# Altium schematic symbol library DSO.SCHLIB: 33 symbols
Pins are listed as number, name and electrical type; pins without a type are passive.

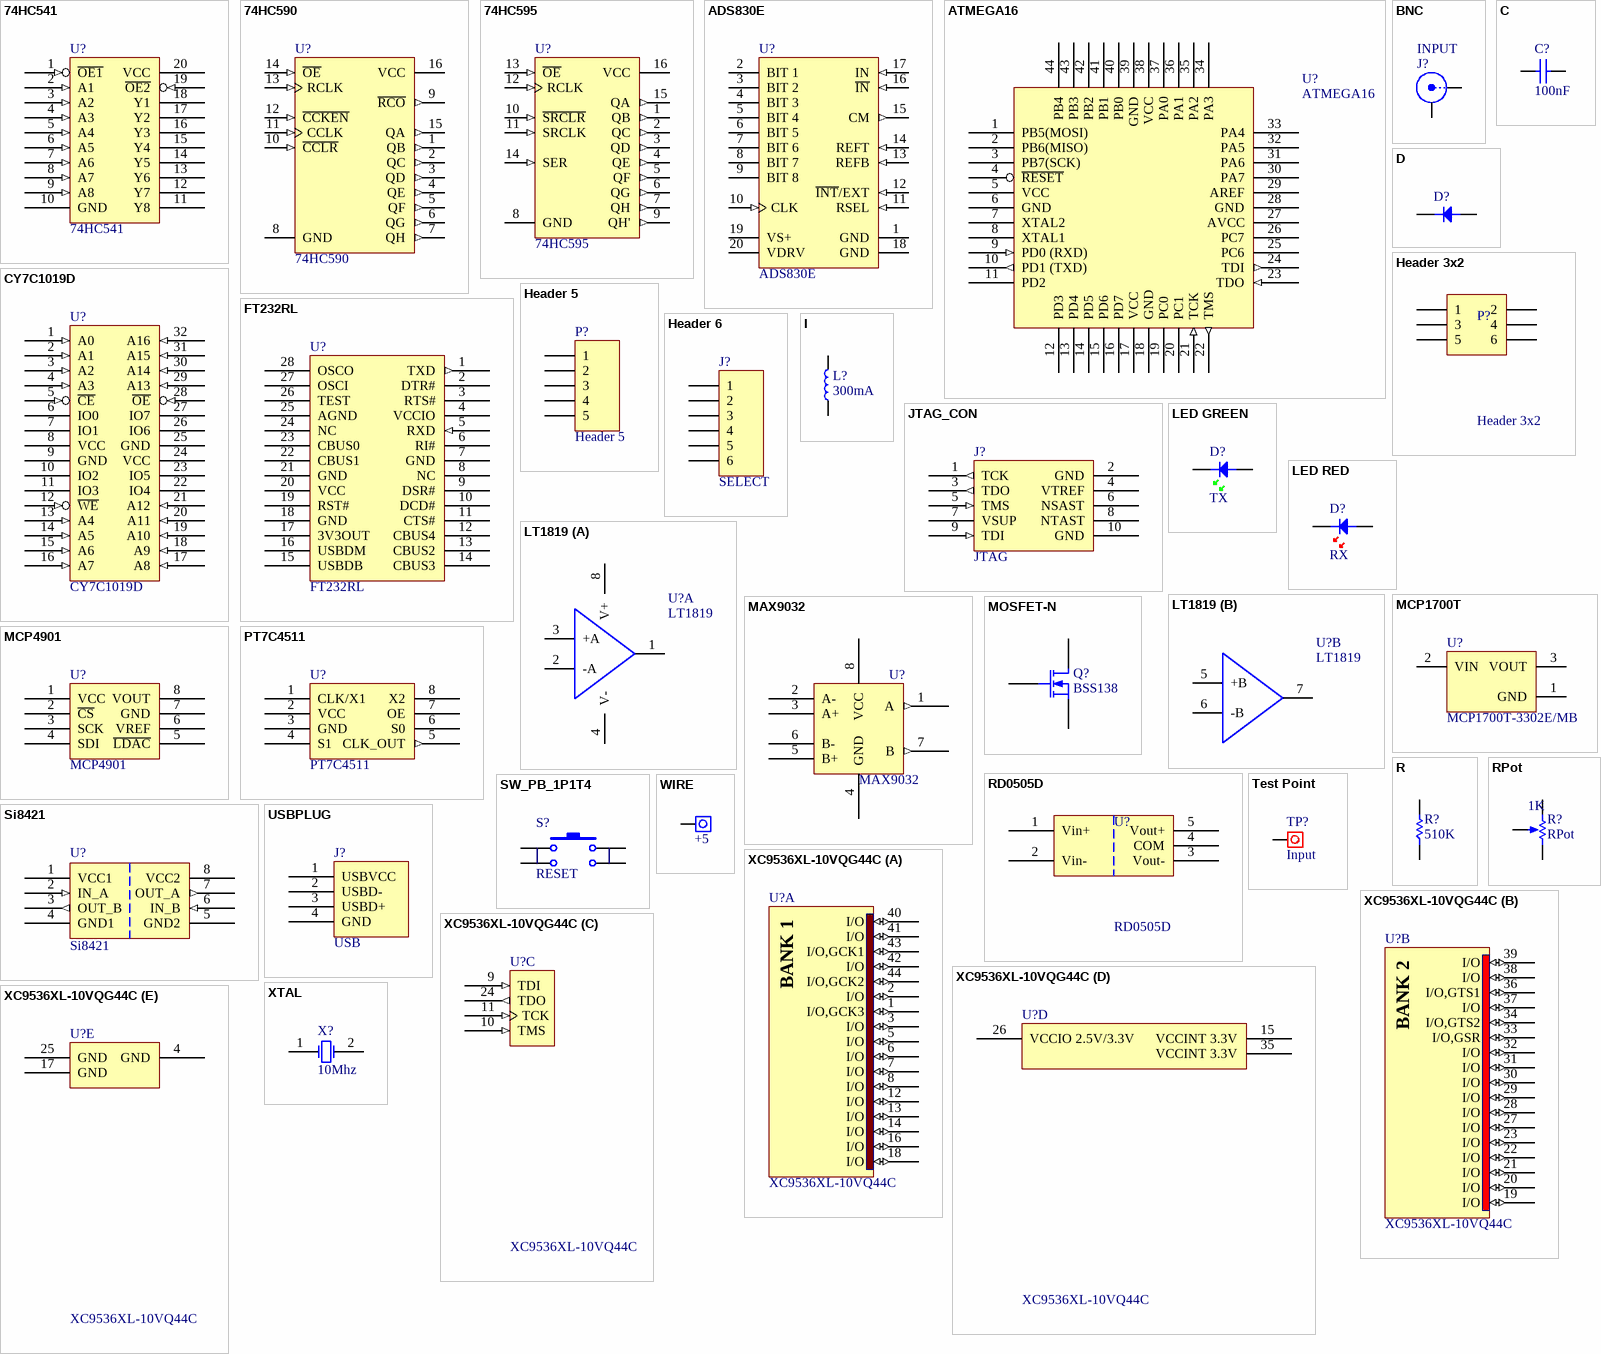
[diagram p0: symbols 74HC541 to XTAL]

## 74HC541
designator U?
(ADV) Octal Buffer, Line Driver; Reviewed by: RM - 2018/08/05
footprint SOT163-1_N (SOIC, 20-Leads, Body 12.7x7.5mm, Pitch 1.27mm, IPC Medium Density)
pins: 1 ~{OE1} (in), 2 A1 (in), 3 A2 (in), 4 A3 (in), 5 A4 (in), 6 A5 (in), 7 A6 (in), 8 A7 (in), 9 A8 (in), 10 GND (power), 11 Y8 (hiz), 12 Y7 (hiz), 13 Y6 (hiz), 14 Y5 (hiz), 15 Y4 (hiz), 16 Y3 (hiz), 17 Y2 (hiz), 18 Y1 (hiz), 19 ~{OE2} (in), 20 VCC (power)

## 74HC590
designator U?
8-Bit Binary Counter Register; Reviewed by: RM - 2018/08/05
footprint SOIC-16 (SOIC-16 Footprint)
pins: 1 QB (out), 2 QC (out), 3 QD (out), 4 QE (out), 5 QF (out), 6 QG (out), 7 QH (out), 8 GND (power), 9 ~{RCO} (out), 10 ~{CCLR} (in), 11 CCLK (in), 12 ~{CCKEN} (in), 13 RCLK (in), 14 ~{OE} (in), 15 QA (out), 16 VCC (power)

## 74HC595
designator U?
(ADV)  8 Bit Shift Register
footprint SOIC-16 (SOIC-16 Footprint)
pins: 1 QB (out), 2 QC (out), 3 QD (out), 4 QE (out), 5 QF (out), 6 QG (out), 7 QH (out), 8 GND (power), 9 QH' (out), 10 ~{SRCLR} (in), 11 SRCLK (in), 12 RCLK (in), 13 ~{OE} (in), 14 SER (in), 15 QA (out), 16 VCC (power)

## ADS830E
designator U?
8-Bit, 60 MSPS ADC Single-Ended / Differential Input, Internal / External Reference and Programmble Input Range, -40 to 85 degC, 20-pin SOP (DBQ20), Green (RoHS & no Sb/Br); Reviewed by: RM - 2018/08/05
footprint TI-DBQ20_L (SOP, 20-Leads, Body 8.65x3.9mm, Pitch 0.635mm, IPC High Density)
pins: 1 GND (power) "Ground", 2 BIT 1 (hiz) "Data Bit 1 (D7) (MSB)", 3 BIT 2 (hiz) "Data Bit 2 (D6)", 4 BIT 3 (hiz) "Data Bit 3 (D5)", 5 BIT 4 (hiz) "Data Bit 4 (D4)", 6 BIT 5 (hiz) "Data Bit 5 (D3)", 7 BIT 6 (hiz) "Data Bit 6 (D2)", 8 BIT 7 (hiz) "Data Bit 7 (D1)", 9 BIT 8 (hiz) "Data Bit 8 (D0) (LSB)", 10 CLK (in) "Convert Clock", 11 RSEL (in) "Input Range Select: HI = 2V; LO = 1V", 12 ~{INT}/EXT (in) "Reference Select: HI = External; LO = Internal", 13 REFB (in) "Bottom Reference", 14 REFT (in) "Top Reference", 15 CM (out) "Common-Mode Voltage Output", 16 ~{IN} (in) "Complementary Input", 17 IN (in) "Analog Input", 18 GND (power) "Ground", 19 VS+ (power) "+5V Supply", 20 VDRV (power) "Output Logic Driver Supply Voltage"

## ATMEGA16
designator U?
ATMEGA16 Microcontroller; Reviewed by: RM - 2018/08/05
footprint QFP-48
pins: 1 PB5(MOSI), 2 PB6(MISO), 3 PB7(SCK), 4 ~{RESET}, 5 VCC, 6 GND, 7 XTAL2, 8 XTAL1, 9 PD0 (RXD) (in), 10 PD1 (TXD) (out), 11 PD2, 12 PD3, 13 PD4, 14 PD5, 15 PD6, 16 PD7, 17 VCC, 18 GND, 19 PC0, 20 PC1, 21 TCK (in), 22 TMS (out), 23 TDO (in), 24 TDI (out), 25 PC6, 26 PC7, 27 AVCC, 28 GND, 29 AREF, 30 PA7, 31 PA6, 32 PA5, 33 PA4, 34 PA3, 35 PA2, 36 PA1, 37 PA0, 38 VCC, 39 GND, 40 PB0, 41 PB1, 42 PB2, 43 PB3, 44 PB4

## BNC
designator J?, comment INPUT
BNC Straight; Reviewed by: RM - 2018/08/05
signal-integrity model Connector
footprint BNC_VERT (BNC vertical connector)
pins: 1 X, 2 Y, 3 Y, 4 Y, 5 Y

## C
designator C?, comment 100nF
Capacitor; Reviewed by: RM - 2018/08/05
simulation model CAP (Default semiconductor capacitor)
footprint 0805C (0805 Footprint)
pins: 1, 2

## CY7C1019D
designator U?
SRAM 128k x 8; Reviewed by: RM - 2018/08/05
footprint TSOP-32
pins: 1 A0 (in), 2 A1 (in), 3 A2 (in), 4 A3 (in), 5 ~{CE} (in), 6 IO0 (hiz), 7 IO1 (hiz), 8 VCC, 9 GND, 10 IO2 (hiz), 11 IO3 (hiz), 12 ~{WE} (in), 13 A4 (in), 14 A5 (in), 15 A6 (in), 16 A7 (in), 17 A8 (in), 18 A9 (in), 19 A10 (in), 20 A11 (in), 21 A12 (in), 22 IO4 (hiz), 23 IO5 (hiz), 24 VCC, 25 GND, 26 IO6 (hiz), 27 IO7 (hiz), 28 ~{OE} (in), 29 A13 (in), 30 A14 (in), 31 A15 (in), 32 A16 (in)

## D
designator D?, comment Diode  (value not drawn)
Reviewed by: RM - 2018/08/05
footprint SOD-123 (SMD diode)
simulation model DIODE (Default Diode)
pins: A, K

## FT232RL
designator U?
USB to Serial bridge; Reviewed by: RM - 2018/08/05
footprint SSOP-28 (Line Driver)
pins: 1 TXD (out), 2 DTR#, 3 RTS#, 4 VCCIO, 5 RXD (in), 6 RI#, 7 GND, 8 NC, 9 DSR#, 10 DCD#, 11 CTS#, 12 CBUS4, 13 CBUS2, 14 CBUS3, 15 USBDB, 16 USBDM, 17 3V3OUT, 18 GND, 19 RST#, 20 VCC, 21 GND, 22 CBUS1, 23 CBUS0, 24 NC, 25 AGND, 26 TEST, 27 OSCI, 28 OSCO

## Header 3x2
designator P?
Header, 5-Pin; Reviewed by: RM - 2018/08/05
signal-integrity model Connector
footprint HDR3x2 (Connector; Header; 8x2 Position)
pins: 1, 2, 3, 4, 5, 6

## Header 5
designator P?
Header, 5-Pin
footprint HDR1X5 (Connector; Header; 5 Position)
signal-integrity model Connector
pins: 1, 2, 3, 4, 5

## Header 6
designator J?, comment SELECT
Header, 6-Pin
footprint HDR1X6 (Connector; Header; 6 Position)
signal-integrity model Connector
pins: 1, 2, 3, 4, 5, 6

## I
designator L?, comment 300mA
Inductor; Reviewed by: RM - 2018/08/05
footprint 0805 (0805 Footprint)
pins: 1, 2

## JTAG_CON
designator J?, comment JTAG
JTAG_CON; Reviewed by: RM - 2018/08/05
footprint BOXEDVERT10 (IDC Header 2.54mm Boxed 10 pins)
pins: 1 TCK (out), 2 GND, 3 TDO (out), 4 VTREF (power), 5 TMS (in), 6 NSAST, 7 VSUP, 8 NTAST, 9 TDI (in), 10 GND

## LED GREEN
designator D?, comment TX
Light Emitting Diode; Reviewed by: RM - 2018/08/05
footprint 0805D-GREEN (0805 Diode)
pins: A, K

## LED RED
designator D?, comment RX
Light Emitting Diode; Reviewed by: RM - 2018/08/05
footprint 0805D-RED (0805 Diode RED)
pins: A, K

## LT1819
designator U?
OpAmp High Frequency Dual; Reviewed by: RM - 2018/08/05
footprint SOIC-8 (SOIC-8 Footprint)
footprint MSOP-8 (TSOP, 8-Leads, Body 3.00x3.00mm, Pitch 0.65mm, IPC Low Density)
part A pins: 1 OUTA, 2 -A, 3 +A, 4 V-, 8 V+
part B pins: 5 +B, 6 -B, 7 OUTB

## MAX9032
designator U?
Dual Comparator; Reviewed by: RM - 2018/08/05
footprint SOIC-8 (SOIC-8 Footprint)
pins: 1 A (out), 2 A-, 3 A+, 4 GND, 5 B+, 6 B-, 7 B (out), 8 VCC

## MCP1700T
designator U?, comment MCP1700T-3302E/MB
Low Quiescent Current LDO, 3-Pin SOT-89, Extended Temperature, Tape and Reel; Reviewed by: RM - 2018/08/05
footprint SOT89 (SOT89, 3-Leads, Body 4.50x2.50mm, Pitch 1.50mm, Lead Span 4.1mm, IPC Low Density)
pins: 1 GND (power), 2 VIN (power), 3 VOUT (power)

## MCP4901
designator U?
DAC 8bit SPI; Reviewed by: RM - 2018/08/05
footprint SOIC-8 (SOIC-8 Footprint)
pins: 1 VCC, 2 ~{CS}, 3 SCK, 4 SDI, 5 ~{LDAC}, 6 VREF, 7 GND, 8 VOUT

## MOSFET-N
designator Q?, comment BSS138
N-Channel MOSFET; PackageDocument: 1995/1996
footprint SOT23 (SOT23, 3-Leads, Body 3.0x2.5mm (max), Pitch 0.95mm, IPC Low Density)
pins: 1, 2, 3

## PT7C4511
designator U?
PLL Clock Multiplier; Reviewed by: RM - 2018/08/05
footprint SOIC-8 (SOIC-8 Footprint)
pins: 1 CLK/X1, 2 VCC, 3 GND, 4 S1, 5 CLK_OUT (out), 6 S0, 7 OE, 8 X2

## R
designator R?, comment 510K
Resistor; Reviewed by: RM - 2018/08/05
footprint 0805 (0805 Footprint)
simulation model RES (Default semiconductor resistor)
pins: 1, 2

## RD0505D
designator U?
(ADV) DC to DC converter 5V in +-5V out; Reviewed by: RM - 2018/08/05
footprint SIP_NMG (SIP for NMG DC to DC)
pins: 1 Vin+, 2 Vin-, 3 Vout-, 4 COM, 5 Vout+

## RPot
designator R?  value 1K
Potentiometer; Sim Note: Enter the Resistance value and the set point into parameter fields.; Set Position: 0.5
footprint VR5 (Thru-Hole; 3 Leads)
pins: 1 TOP, 2 TAP, 3 BOT
1 alternate drawing of the same symbol

## Si8421
designator U?
Dual Channel Digital Isolator Both Ways; Reviewed by: RM - 2018/08/05
footprint SOIC-8 (SOIC-8 Footprint)
pins: 1 VCC1, 2 IN_A (in), 3 OUT_B (out), 4 GND1, 5 GND2, 6 IN_B (in), 7 OUT_A (out), 8 VCC2

## SW_PB_1P1T4
designator S?, comment RESET
Momentary Push Button Switch 1P 1T 2pins; Reviewed by: RM - 2018/08/05
footprint SPST PB SWITCH SMD (Push Button Switch Surface Mount)
pins: 1, 2, 3, 4

## Test Point
designator TP?, comment INPUT
Pad
footprint Testpoin (Testpoint)
pins: 1

## USBPLUG
designator J?, comment USB
USB B Type Connector; Reviewed by: RM - 2018/08/05
footprint USBPLUG
pins: 1 USBVCC, 2 USBD-, 3 USBD+, 4 GND

## WIRE
designator TP?, comment +5
Pad
footprint PIN 1.8mm (Single Pin)
pins: 1

## XC9536XL-10VQG44C
designator U?, comment XC9536XL-10VQ44C
FastFLASH XC900XL, 3.3V High-Performance 36 Macrocell CPLD, 34 User I/Os, 44-Pin VQFP, Speed Grade 10, Commercial Grade; Reviewed by: RM - 2018/08/05
footprint VQ44_L (Thin QFP, 44-Leads, Body 10x10mm, Pitch 0.8mm, IPC High Density)
part A pins: 1 I/O,GCK3 (io), 2 I/O (io), 3 I/O (io), 5 I/O (io), 6 I/O (io), 7 I/O (io), 8 I/O (io), 12 I/O (io), 13 I/O (io), 14 I/O (io), 16 I/O (io), 18 I/O (io), 40 I/O (io), 41 I/O (io), 42 I/O (io), 43 I/O,GCK1 (io), 44 I/O,GCK2 (io)
part B pins: 19 I/O (io), 20 I/O (io), 21 I/O (io), 22 I/O (io), 23 I/O (io), 27 I/O (io), 28 I/O (io), 29 I/O (io), 30 I/O (io), 31 I/O (io), 32 I/O (io), 33 I/O,GSR (io), 34 I/O,GTS2 (io), 36 I/O,GTS1 (io), 37 I/O (io), 38 I/O (io), 39 I/O (io)
part C pins: 9 TDI (in), 10 TMS (in), 11 TCK (in), 24 TDO (out)
part D pins: 15 VCCINT 3.3V (power), 26 VCCIO 2.5V/3.3V (power), 35 VCCINT 3.3V (power)
part E pins: 4 GND (power), 17 GND (power), 25 GND (power)

## XTAL
designator X?, comment 10Mhz
Crystal Oscillator; Reviewed by: RM - 2018/08/05
simulation model XTAL (Spice Subcircuit)
footprint XTAL_FLAT_SMD
pins: 1 OSC1, 2 OSC2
